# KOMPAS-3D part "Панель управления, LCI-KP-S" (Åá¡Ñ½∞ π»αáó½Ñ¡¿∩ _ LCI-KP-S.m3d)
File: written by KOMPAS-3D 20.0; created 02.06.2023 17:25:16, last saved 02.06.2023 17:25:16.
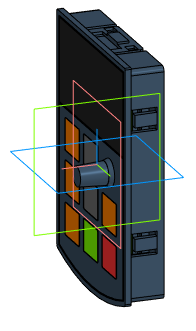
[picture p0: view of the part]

Document properties: Автор: admin; Полное имя файла: P:\INSTART\Технический отдел\ОР\Прочие задачи\КД на номенклатурный ряд\КД на панели управления ПЧ\LCI\Панель управления _ LCI-KP-S.m3d

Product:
- Part/product: Панель управления  | designation LCI-KP-S

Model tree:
1. Поверхность без истории:1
